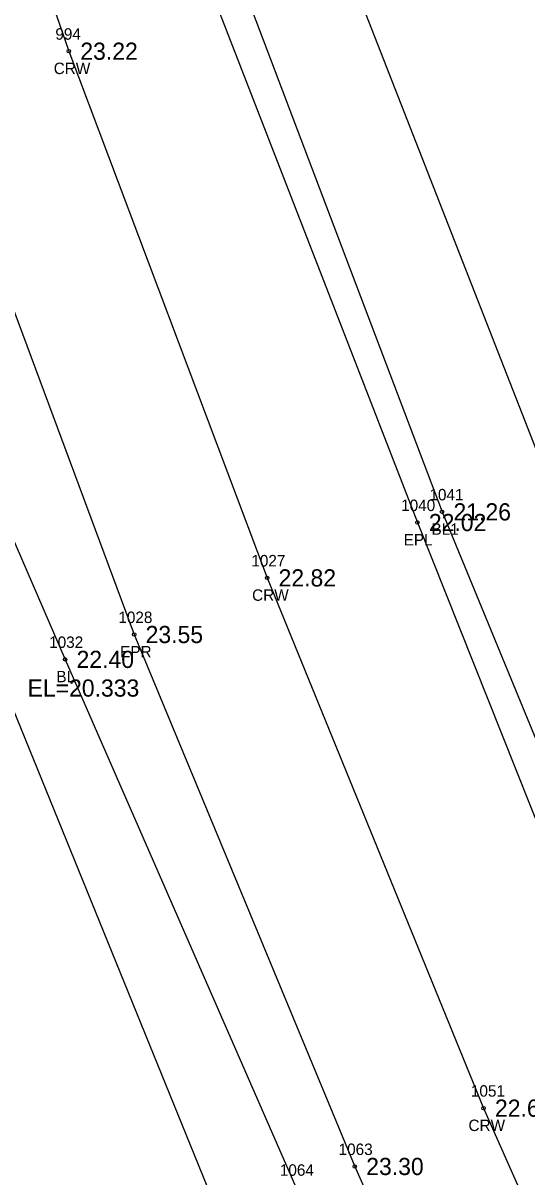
# Model space of a CAD drawing. Extents: x 2042211 to 2045853, y 303080 to 309569.
# Drawn here: x 2042949.1 to 2042993, y 306601.3 to 306702 of the extents above; entities that cross this region are included whole.
import ezdxf

# ---------------------------------------------------------------- set-up
doc = ezdxf.new("R2010")
doc.units = 0
for name, color, linetype in [('RD_DTM_BkLn1', 7, 'Continuous'), ('RD_DTM_BkLn_txCode', 7, 'Continuous'), ('RD_EX_H2O', 7, 'Continuous'), ('RD_EX_Road', 7, 'Continuous'), ('RD_EX_Road_txCode', 7, 'Continuous'), ('RD_EX_TX_H2O_ELEV', 7, 'Continuous'), ('RD_EX_TX_Misc_ELEV', 7, 'Continuous'), ('RD_EX_TX_Road_ELEV', 7, 'Continuous'), ('RD_HC_Survey_ELEV', 7, 'Continuous'), ('RD_HC_Survey_txCode', 7, 'Continuous'), ('RD_SMD_Locator', 7, 'Continuous')]:
    doc.layers.add(name, color=color, linetype=linetype)

msp = doc.modelspace()

# ---------------------------------------------------------------- linework, layer by layer
at = {"layer": 'RD_DTM_BkLn1'}
for points in [[(2042839.81, 307329.37), (2042840.93, 307280.46), (2042843.39, 307231.17), (2042846.87, 307181.66), (2042851.76, 307132.07), (2042857.83, 307083.36), (2042865.03, 307034.36), (2042873.56, 306985.67), (2042883.71, 306937.59), (2042895.32, 306889.27), (2042908.01, 306841.41), (2042921.81, 306793.88), (2042936.83, 306746.34), (2042953.05, 306699.55), (2042970.36, 306653.6), (2042989.25, 306607.34), (2043009.36, 306561.99), (2043030.44, 306517.39), (2043052.89, 306472.91), (2043076.3, 306429.26), (2043100.43, 306386.21)], [(2042857.66, 307329.64), (2042861.09, 307281.84), (2042862.27, 307232.19), (2042866.29, 307183.84), (2042870.56, 307134.28), (2042875.48, 307086.26), (2042882.95, 307037.68), (2042891.21, 306988.93), (2042900.82, 306941.19), (2042911.81, 306893.75), (2042924.4, 306846), (2042938.51, 306799.29), (2042953.5, 306752.33), (2042968.09, 306705.62), (2042985.63, 306659.36), (2043004.49, 306613.62), (2043024.61, 306569.26), (2043045.97, 306525.25), (2043068.43, 306480.84), (2043092.42, 306438.64), (2043116.55, 306395.12)], [(2042839.17, 307095.11), (2042841.19, 307080.52), (2042848.71, 307031.33), (2042857.64, 306982.34), (2042868.25, 306933.78), (2042879.62, 306884.9), (2042891.37, 306836.61), (2042906.05, 306788.56), (2042920.38, 306740.36), (2042936.3, 306692.68), (2042942.2, 306670.77), (2042952.72, 306646.49), (2042972.88, 306600.44), (2042993.94, 306554.96), (2043015.19, 306509.48), (2043037.06, 306464.5), (2043060.22, 306420.45)]]:
    msp.add_lwpolyline(points, dxfattribs=at)
at = {"layer": 'RD_EX_H2O'}
for points in [[(2042866.82, 307329.93), (2042876.23, 307282.16), (2042878.43, 307232.86), (2042875.08, 307184.77), (2042887.19, 307136.65), (2042884.32, 307120.02), (2042882.74, 307087.49), (2042892.51, 307039.16), (2042896.41, 306990.42), (2042899.37, 306973.37), (2042910.05, 306942.23), (2042920.75, 306896.67), (2042927.15, 306846.78), (2042945.6, 306801.59), (2042960.32, 306754.61), (2042976.65, 306708.74), (2042994.63, 306662.76), (2043013.3, 306616.98), (2043029.17, 306571.91), (2043050.77, 306528.53)], [(2042812.2, 307117.75), (2042817.66, 307076.99), (2042828.97, 307027.39), (2042840.42, 306978.95), (2042848.44, 306929.66), (2042859.84, 306880.36), (2042873.68, 306831.67), (2042888.54, 306783.43), (2042900.59, 306749.27), (2042902.9, 306733.67), (2042926.04, 306688.21), (2042936.45, 306668.37), (2042947.44, 306643.99), (2042966.18, 306597.91), (2042985.34, 306551.14), (2042987.61, 306538.59)]]:
    msp.add_lwpolyline(points, dxfattribs=at)
at = {"layer": 'RD_EX_Road'}
for points in [[(2042853.31, 307329.44), (2042854.43, 307281.38), (2042857.15, 307232.07), (2042860.27, 307183.35), (2042865.16, 307133.89), (2042871.37, 307085.7), (2042878.53, 307037.13), (2042886.97, 306988.21), (2042897.02, 306940.01), (2042908.28, 306892.66), (2042921.09, 306844.85), (2042934.41, 306798.2), (2042949.37, 306750.96), (2042965.62, 306704.44), (2042983.48, 306658.43), (2043001.91, 306612.18), (2043021.64, 306567.98), (2043042.58, 306523.81), (2043065.05, 306479.23), (2043088.14, 306436.09), (2043112.53, 306392.81)], [(2042895.94, 306837.56), (2042909.76, 306789.89), (2042925.08, 306742.02), (2042941.49, 306695.02), (2042958.75, 306648.66), (2042978.01, 306602.25), (2042998.08, 306556.93), (2043019.38, 306511.63), (2043041.84, 306466.86), (2043065.03, 306422.83)]]:
    msp.add_lwpolyline(points, dxfattribs=at)
at = {"layer": 'RD_SMD_Locator'}
for centre in [(2042953.05, 306699.55), (2042985.63, 306659.36), (2042983.48, 306658.43), (2042970.36, 306653.6), (2042958.75, 306648.66), (2042952.72, 306646.49), (2042989.25, 306607.34), (2042978.01, 306602.25)]:
    msp.add_circle(centre, 0.15, dxfattribs=at)

# ---------------------------------------------------------------- texts
at = {"layer": 'RD_DTM_BkLn_txCode'}
for s, p in [('1041', (2042984.53, 306660.36)), ('BL1', (2042984.71, 306657.36)), ('1032', (2042951.33, 306647.49)), ('BL', (2042951.96, 306644.49)), ('1064', (2042971.47, 306601.44))]:
    msp.add_text(s, height=1, dxfattribs=at).set_placement(p)
at = {"layer": 'RD_EX_Road_txCode'}
for s, p in [('1040', (2042982.06, 306659.43)), ('EPL', (2042982.28, 306656.43)), ('1028', (2042957.37, 306649.66)), ('EPR', (2042957.52, 306646.66)), ('1063', (2042976.6, 306603.25))]:
    msp.add_text(s, height=1, dxfattribs=at).set_placement(p)
at = {"layer": 'RD_EX_TX_H2O_ELEV'}
msp.add_text('EL=20.333', height=1.5, dxfattribs=at).set_placement((2042949.44, 306643.24))
at = {"layer": 'RD_EX_TX_Misc_ELEV'}
for s, p in [('21.26', (2042986.63, 306658.61)), ('22.40', (2042953.72, 306645.74))]:
    msp.add_text(s, height=1.5, dxfattribs=at).set_placement(p)
at = {"layer": 'RD_EX_TX_Road_ELEV'}
for s, p in [('22.02', (2042984.48, 306657.68)), ('23.55', (2042959.75, 306647.91)), ('23.30', (2042979.01, 306601.5))]:
    msp.add_text(s, height=1.5, dxfattribs=at).set_placement(p)
at = {"layer": 'RD_HC_Survey_ELEV'}
for s, p in [('23.22', (2042954.05, 306698.8)), ('22.82', (2042971.36, 306652.85)), ('22.64', (2042990.25, 306606.59))]:
    msp.add_text(s, height=1.5, dxfattribs=at).set_placement(p)
at = {"layer": 'RD_HC_Survey_txCode'}
for s, p in [('994', (2042951.87, 306700.55)), ('CRW', (2042951.73, 306697.55)), ('1027', (2042968.98, 306654.6)), ('CRW', (2042969.05, 306651.6)), ('1051', (2042988.15, 306608.34)), ('CRW', (2042987.94, 306605.34))]:
    msp.add_text(s, height=1, dxfattribs=at).set_placement(p)

doc.saveas('drawing.dxf')
